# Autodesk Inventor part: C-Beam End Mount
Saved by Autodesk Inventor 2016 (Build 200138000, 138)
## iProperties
Created: 2016-03
Part Number: C-Beam End Mount
Material: Generic
Document SubType Name: Modeling
Designer: bongo_000
Density: 1 g/cm^3
Appearance: Default
Author: bongo_000
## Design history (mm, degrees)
feature "CUT-EXTRUDE2"
body "Solid1"
